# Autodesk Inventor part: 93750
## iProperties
Author: Administrator
Shininess: 64.0
Angle Display Precision: 2
Document Length Units: 11272
Document Angle Units: 11286
Document Time Units: 11279
Document Mass Units: 11290
Document Length Units Precision: 3
Document Angle Units Precision: 2
Compacted: True
PropertySet Name: _Private Model Information
Created: 2002-03
Part Number: 93750
Material: Stainless Steel, 440C
Document SubType Name: Modeling
Designer: Administrator
Control State: 0
Master: False
Checked Out: False
PropertySet Name: Design Tracking Control
Density: 0.0
Volumn: 0.0
Area: 0.0
PropertySet Name: Model Information
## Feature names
1. Revolution1
